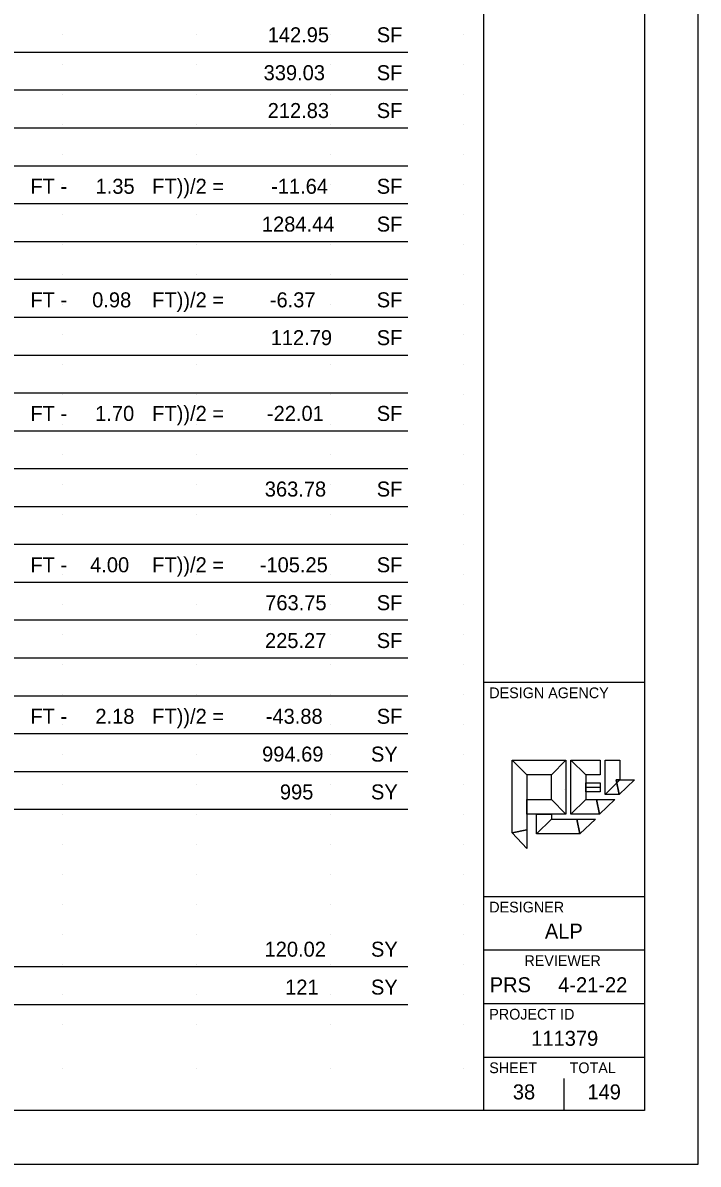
# Model space of a CAD drawing. Extents: x 2073163.5 to 2073197.5, y 634076.4 to 634098.4.
# Drawn here: x 2073191.2 to 2073197.51, y 634076.43 to 634087.09 of the extents above; entities that cross this region are included whole.
import ezdxf

# ---------------------------------------------------------------- set-up
doc = ezdxf.new("R2010")
doc.units = 0
for name, color, linetype in [('Default', 7, 'Continuous'), ('SC_Scratch1', 7, 'Continuous'), ('SH_Border', 7, 'Continuous'), ('SH_Cut_Line', 7, 'Continuous'), ('SH_Data', 7, 'Continuous'), ('SH_Text', 7, 'Continuous')]:
    doc.layers.add(name, color=color, linetype=linetype)

msp = doc.modelspace()

# ---------------------------------------------------------------- linework, layer by layer
at = {"layer": 'Default'}
msp.add_line((2073196.457, 634079.953), (2073196.593, 634079.953), dxfattribs=at)
for points in [[(2073195.77, 634079.527), (2073195.77, 634080.204), (2073195.908, 634080.067), (2073195.908, 634079.556)], [(2073195.77, 634080.204), (2073196.273, 634080.204), (2073196.137, 634080.067), (2073195.908, 634080.067)], [(2073196.273, 634080.204), (2073196.273, 634079.702), (2073196.137, 634079.839), (2073196.137, 634080.067)], [(2073196.319, 634079.702), (2073196.319, 634080.204), (2073196.457, 634080.067), (2073196.457, 634079.839)], [(2073196.319, 634080.204), (2073196.593, 634080.204), (2073196.593, 634080.067), (2073196.457, 634080.067)], [(2073196.639, 634079.884), (2073196.639, 634080.204), (2073196.777, 634080.204), (2073196.777, 634080.022)], [(2073196.593, 634079.994), (2073196.593, 634079.911), (2073196.458, 634079.911), (2073196.458, 634079.994)], [(2073196.768, 634079.884), (2073196.639, 634079.884), (2073196.777, 634080.022), (2073196.74, 634080.022)], [(2073196.913, 634080.022), (2073196.768, 634079.884), (2073196.74, 634080.022)], [(2073196.273, 634079.702), (2073195.908, 634079.702), (2073195.908, 634079.839), (2073196.137, 634079.839)], [(2073196.585, 634079.702), (2073196.319, 634079.702), (2073196.457, 634079.839), (2073196.557, 634079.839)], [(2073196.73, 634079.839), (2073196.585, 634079.702), (2073196.557, 634079.839)], [(2073195.999, 634079.519), (2073195.999, 634079.702), (2073196.137, 634079.702), (2073196.137, 634079.656)], [(2073196.402, 634079.519), (2073195.999, 634079.519), (2073196.137, 634079.656), (2073196.373, 634079.656)], [(2073196.548, 634079.656), (2073196.402, 634079.519), (2073196.373, 634079.656)], [(2073195.908, 634079.382), (2073195.77, 634079.527), (2073195.908, 634079.556)]]:
    msp.add_lwpolyline(points, close=True, dxfattribs=at)
at = {"layer": 'SC_Scratch1'}
for p, q in [((2073180.369, 634086.814), (2073194.796, 634086.814)), ((2073180.369, 634086.461), (2073194.796, 634086.461)), ((2073180.369, 634086.107), (2073194.796, 634086.107)), ((2073180.369, 634085.754), (2073194.796, 634085.754)), ((2073180.369, 634085.401), (2073194.796, 634085.401)), ((2073180.369, 634085.047), (2073194.796, 634085.047)), ((2073180.369, 634084.694), (2073194.796, 634084.694)), ((2073180.369, 634084.34), (2073194.796, 634084.34)), ((2073180.369, 634083.987), (2073194.796, 634083.987)), ((2073180.369, 634083.634), (2073194.796, 634083.634)), ((2073180.369, 634083.28), (2073194.796, 634083.28)), ((2073180.369, 634082.927), (2073194.796, 634082.927)), ((2073180.369, 634082.574), (2073194.796, 634082.574)), ((2073180.369, 634082.22), (2073194.796, 634082.22)), ((2073180.369, 634081.867), (2073194.796, 634081.867)), ((2073180.369, 634081.514), (2073194.796, 634081.514)), ((2073180.369, 634081.16), (2073194.796, 634081.16)), ((2073180.369, 634080.807), (2073194.796, 634080.807)), ((2073180.369, 634080.454), (2073194.796, 634080.454)), ((2073180.369, 634080.1), (2073194.796, 634080.1)), ((2073180.369, 634079.747), (2073194.796, 634079.747)), ((2073180.369, 634078.279), (2073194.796, 634078.279)), ((2073180.369, 634077.926), (2073194.796, 634077.926))]:
    msp.add_line(p, q, dxfattribs=at)
at = {"layer": 'SH_Border'}
for p, q in [((2073195.507, 634076.934), (2073195.507, 634097.934)), ((2073195.507, 634080.934), (2073197.007, 634080.934)), ((2073195.507, 634078.934), (2073197.007, 634078.934)), ((2073195.507, 634078.434), (2073197.007, 634078.434)), ((2073195.507, 634077.934), (2073197.007, 634077.934)), ((2073195.507, 634077.434), (2073197.007, 634077.434))]:
    msp.add_line(p, q, dxfattribs=at)
msp.add_lwpolyline([(2073165.007, 634097.934), (2073197.007, 634097.934), (2073197.007, 634076.934), (2073165.007, 634076.934)], close=True, dxfattribs=at)
at = {"layer": 'SH_Cut_Line'}
msp.add_lwpolyline([(2073163.507, 634076.434), (2073197.507, 634076.434), (2073197.507, 634098.434), (2073163.507, 634098.434)], close=True, dxfattribs=at)
at = {"layer": 'SH_Data'}
for p, q in [((2073191.571, 634086.978), (2073191.571, 634086.978)), ((2073192.821, 634086.978), (2073192.821, 634086.978)), ((2073194.071, 634086.978), (2073194.071, 634086.978)), ((2073195.321, 634086.978), (2073195.321, 634086.978)), ((2073191.571, 634086.698), (2073191.571, 634086.698)), ((2073192.821, 634086.698), (2073192.821, 634086.698)), ((2073194.071, 634086.698), (2073194.071, 634086.698)), ((2073195.321, 634086.698), (2073195.321, 634086.698)), ((2073191.571, 634086.418), (2073191.571, 634086.418)), ((2073192.821, 634086.418), (2073192.821, 634086.418)), ((2073194.071, 634086.418), (2073194.071, 634086.418)), ((2073195.321, 634086.418), (2073195.321, 634086.418)), ((2073191.571, 634086.138), (2073191.571, 634086.138)), ((2073192.821, 634086.138), (2073192.821, 634086.138)), ((2073194.071, 634086.138), (2073194.071, 634086.138)), ((2073195.321, 634086.138), (2073195.321, 634086.138)), ((2073191.571, 634085.858), (2073191.571, 634085.858)), ((2073192.821, 634085.858), (2073192.821, 634085.858)), ((2073194.071, 634085.858), (2073194.071, 634085.858)), ((2073195.321, 634085.858), (2073195.321, 634085.858)), ((2073191.571, 634085.578), (2073191.571, 634085.578)), ((2073192.821, 634085.578), (2073192.821, 634085.578)), ((2073194.071, 634085.578), (2073194.071, 634085.578)), ((2073195.321, 634085.578), (2073195.321, 634085.578)), ((2073191.571, 634085.298), (2073191.571, 634085.298)), ((2073192.821, 634085.298), (2073192.821, 634085.298)), ((2073194.071, 634085.298), (2073194.071, 634085.298)), ((2073195.321, 634085.298), (2073195.321, 634085.298)), ((2073191.571, 634085.018), (2073191.571, 634085.018)), ((2073192.821, 634085.018), (2073192.821, 634085.018)), ((2073194.071, 634085.018), (2073194.071, 634085.018)), ((2073195.321, 634085.018), (2073195.321, 634085.018)), ((2073191.571, 634084.738), (2073191.571, 634084.738)), ((2073192.821, 634084.738), (2073192.821, 634084.738)), ((2073194.071, 634084.738), (2073194.071, 634084.738)), ((2073195.321, 634084.738), (2073195.321, 634084.738)), ((2073191.571, 634084.458), (2073191.571, 634084.458)), ((2073192.821, 634084.458), (2073192.821, 634084.458)), ((2073194.071, 634084.458), (2073194.071, 634084.458)), ((2073195.321, 634084.458), (2073195.321, 634084.458)), ((2073191.571, 634084.178), (2073191.571, 634084.178)), ((2073192.821, 634084.178), (2073192.821, 634084.178)), ((2073194.071, 634084.178), (2073194.071, 634084.178)), ((2073195.321, 634084.178), (2073195.321, 634084.178)), ((2073191.571, 634083.898), (2073191.571, 634083.898)), ((2073192.821, 634083.898), (2073192.821, 634083.898)), ((2073194.071, 634083.898), (2073194.071, 634083.898)), ((2073195.321, 634083.898), (2073195.321, 634083.898)), ((2073191.571, 634083.618), (2073191.571, 634083.618)), ((2073192.821, 634083.618), (2073192.821, 634083.618)), ((2073194.071, 634083.618), (2073194.071, 634083.618)), ((2073195.321, 634083.618), (2073195.321, 634083.618)), ((2073191.571, 634083.338), (2073191.571, 634083.338)), ((2073192.821, 634083.338), (2073192.821, 634083.338)), ((2073194.071, 634083.338), (2073194.071, 634083.338)), ((2073195.321, 634083.338), (2073195.321, 634083.338)), ((2073191.571, 634083.058), (2073191.571, 634083.058)), ((2073192.821, 634083.058), (2073192.821, 634083.058)), ((2073194.071, 634083.058), (2073194.071, 634083.058)), ((2073195.321, 634083.058), (2073195.321, 634083.058)), ((2073191.571, 634082.778), (2073191.571, 634082.778)), ((2073192.821, 634082.778), (2073192.821, 634082.778)), ((2073194.071, 634082.778), (2073194.071, 634082.778)), ((2073195.321, 634082.778), (2073195.321, 634082.778)), ((2073191.571, 634082.498), (2073191.571, 634082.498)), ((2073192.821, 634082.498), (2073192.821, 634082.498)), ((2073194.071, 634082.498), (2073194.071, 634082.498)), ((2073195.321, 634082.498), (2073195.321, 634082.498)), ((2073191.571, 634082.218), (2073191.571, 634082.218)), ((2073192.821, 634082.218), (2073192.821, 634082.218)), ((2073194.071, 634082.218), (2073194.071, 634082.218)), ((2073195.321, 634082.218), (2073195.321, 634082.218)), ((2073191.571, 634081.938), (2073191.571, 634081.938)), ((2073192.821, 634081.938), (2073192.821, 634081.938)), ((2073194.071, 634081.938), (2073194.071, 634081.938)), ((2073195.321, 634081.938), (2073195.321, 634081.938)), ((2073191.571, 634081.658), (2073191.571, 634081.658)), ((2073192.821, 634081.658), (2073192.821, 634081.658)), ((2073194.071, 634081.658), (2073194.071, 634081.658)), ((2073195.321, 634081.658), (2073195.321, 634081.658)), ((2073191.571, 634081.378), (2073191.571, 634081.378)), ((2073192.821, 634081.378), (2073192.821, 634081.378)), ((2073194.071, 634081.378), (2073194.071, 634081.378)), ((2073195.321, 634081.378), (2073195.321, 634081.378)), ((2073191.571, 634081.098), (2073191.571, 634081.098)), ((2073192.821, 634081.098), (2073192.821, 634081.098)), ((2073194.071, 634081.098), (2073194.071, 634081.098)), ((2073195.321, 634081.098), (2073195.321, 634081.098)), ((2073191.571, 634080.818), (2073191.571, 634080.818)), ((2073192.821, 634080.818), (2073192.821, 634080.818)), ((2073194.071, 634080.818), (2073194.071, 634080.818)), ((2073195.321, 634080.818), (2073195.321, 634080.818)), ((2073191.571, 634080.538), (2073191.571, 634080.538)), ((2073192.821, 634080.538), (2073192.821, 634080.538)), ((2073194.071, 634080.538), (2073194.071, 634080.538)), ((2073195.321, 634080.538), (2073195.321, 634080.538)), ((2073191.571, 634080.258), (2073191.571, 634080.258)), ((2073192.821, 634080.258), (2073192.821, 634080.258)), ((2073194.071, 634080.258), (2073194.071, 634080.258)), ((2073195.321, 634080.258), (2073195.321, 634080.258)), ((2073191.571, 634079.978), (2073191.571, 634079.978)), ((2073192.821, 634079.978), (2073192.821, 634079.978)), ((2073194.071, 634079.978), (2073194.071, 634079.978)), ((2073195.321, 634079.978), (2073195.321, 634079.978)), ((2073196.257, 634079.934), (2073196.257, 634079.934)), ((2073191.571, 634079.698), (2073191.571, 634079.698)), ((2073192.821, 634079.698), (2073192.821, 634079.698)), ((2073194.071, 634079.698), (2073194.071, 634079.698)), ((2073195.321, 634079.698), (2073195.321, 634079.698)), ((2073191.571, 634079.418), (2073191.571, 634079.418)), ((2073192.821, 634079.418), (2073192.821, 634079.418)), ((2073194.071, 634079.418), (2073194.071, 634079.418)), ((2073195.321, 634079.418), (2073195.321, 634079.418)), ((2073191.571, 634079.138), (2073191.571, 634079.138)), ((2073192.821, 634079.138), (2073192.821, 634079.138)), ((2073194.071, 634079.138), (2073194.071, 634079.138)), ((2073195.321, 634079.138), (2073195.321, 634079.138)), ((2073191.571, 634078.858), (2073191.571, 634078.858)), ((2073192.821, 634078.858), (2073192.821, 634078.858)), ((2073194.071, 634078.858), (2073194.071, 634078.858)), ((2073195.321, 634078.858), (2073195.321, 634078.858)), ((2073191.571, 634078.578), (2073191.571, 634078.578)), ((2073192.821, 634078.578), (2073192.821, 634078.578)), ((2073194.071, 634078.578), (2073194.071, 634078.578)), ((2073195.321, 634078.578), (2073195.321, 634078.578)), ((2073191.571, 634078.298), (2073191.571, 634078.298)), ((2073192.821, 634078.298), (2073192.821, 634078.298)), ((2073194.071, 634078.298), (2073194.071, 634078.298)), ((2073195.321, 634078.298), (2073195.321, 634078.298)), ((2073191.571, 634078.018), (2073191.571, 634078.018)), ((2073192.821, 634078.018), (2073192.821, 634078.018)), ((2073194.071, 634078.018), (2073194.071, 634078.018)), ((2073195.321, 634078.018), (2073195.321, 634078.018)), ((2073191.571, 634077.738), (2073191.571, 634077.738)), ((2073192.821, 634077.738), (2073192.821, 634077.738)), ((2073194.071, 634077.738), (2073194.071, 634077.738)), ((2073195.321, 634077.738), (2073195.321, 634077.738)), ((2073191.571, 634077.324), (2073191.571, 634077.324)), ((2073192.821, 634077.324), (2073192.821, 634077.324)), ((2073194.071, 634077.324), (2073194.071, 634077.324)), ((2073195.321, 634077.324), (2073195.321, 634077.324)), ((2073196.257, 634076.934), (2073196.257, 634077.234)), ((2073195.882, 634077.109), (2073195.882, 634077.109))]:
    msp.add_line(p, q, dxfattribs=at)

# ---------------------------------------------------------------- texts
for s, height, p in [('DESIGN AGENCY', 0.1, (2073195.557, 634080.784)), ('DESIGNER', 0.1, (2073195.557, 634078.784)), ('ALP', 0.14, (2073196.076, 634078.539)), ('REVIEWER', 0.1, (2073195.885, 634078.284)), ('PRS', 0.14, (2073195.561, 634078.039)), ('4-21-22', 0.14, (2073196.2, 634078.039)), ('PROJECT ID', 0.1, (2073195.557, 634077.784)), ('111379', 0.14, (2073195.949, 634077.539)), ('SHEET', 0.1, (2073195.557, 634077.284)), ('TOTAL', 0.1, (2073196.307, 634077.284)), ('38', 0.14, (2073195.777, 634077.039)), ('149', 0.14, (2073196.473, 634077.039))]:
    msp.add_text(s, height=height, dxfattribs=at).set_placement(p)
at = {"layer": 'SH_Text'}
for s, p in [('142.95', (2073193.489, 634086.906)), ('SF ', (2073194.507, 634086.906)), ('339.03', (2073193.451, 634086.552)), ('SF ', (2073194.507, 634086.552)), ('212.83', (2073193.489, 634086.199)), ('SF ', (2073194.507, 634086.199)), ('FT -', (2073191.275, 634085.492)), ('1.35', (2073191.883, 634085.492)), ('FT))/2 =', (2073192.411, 634085.492)), ('-11.64', (2073193.521, 634085.492)), ('SF ', (2073194.507, 634085.492)), ('1284.44', (2073193.435, 634085.139)), ('SF ', (2073194.507, 634085.139)), ('FT -', (2073191.275, 634084.432)), ('0.98', (2073191.851, 634084.432)), ('FT))/2 =', (2073192.411, 634084.432)), ('-6.37', (2073193.509, 634084.432)), ('SF ', (2073194.507, 634084.432)), ('112.79', (2073193.517, 634084.079)), ('SF ', (2073194.507, 634084.079)), ('FT -', (2073191.275, 634083.372)), ('1.70', (2073191.879, 634083.372)), ('FT))/2 =', (2073192.411, 634083.372)), ('-22.01', (2073193.482, 634083.372)), ('SF ', (2073194.507, 634083.372)), ('363.78', (2073193.462, 634082.666)), ('SF ', (2073194.507, 634082.666)), ('FT -', (2073191.275, 634081.959)), ('4.00', (2073191.832, 634081.959)), ('FT))/2 =', (2073192.411, 634081.959)), ('-105.25', (2073193.415, 634081.959)), ('SF ', (2073194.507, 634081.959)), ('763.75', (2073193.466, 634081.605)), ('SF ', (2073194.507, 634081.605)), ('225.27', (2073193.464, 634081.252)), ('SF ', (2073194.507, 634081.252)), ('FT -', (2073191.275, 634080.545)), ('2.18', (2073191.881, 634080.545)), ('FT))/2 =', (2073192.411, 634080.545)), ('-43.88', (2073193.471, 634080.545)), ('SF ', (2073194.507, 634080.545)), ('994.69', (2073193.437, 634080.192)), ('SY', (2073194.453, 634080.192)), ('995', (2073193.603, 634079.839)), ('SY', (2073194.453, 634079.839)), ('120.02', (2073193.46, 634078.371)), ('SY', (2073194.453, 634078.371)), ('121', (2073193.652, 634078.017)), ('SY', (2073194.453, 634078.017))]:
    msp.add_text(s, height=0.14, rotation=0.0001, dxfattribs=at).set_placement(p)

doc.saveas('drawing.dxf')
